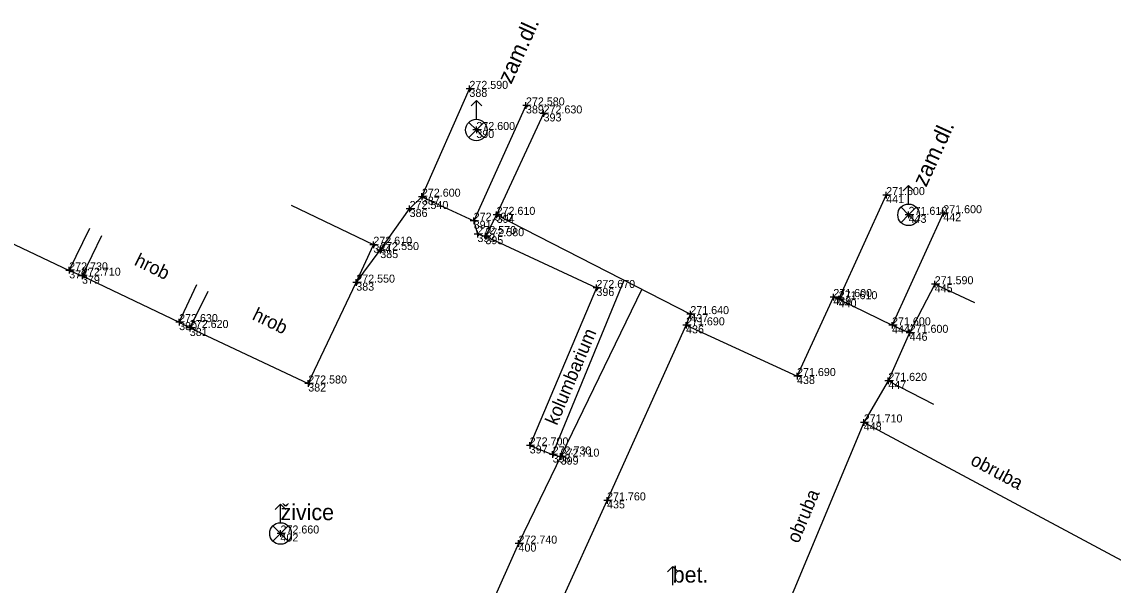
# Model space of a CAD drawing. Extents: x -776606 to -776076, y -974328 to -973875.
# Drawn here: x -776349.29 to -776328.84, y -974207.62 to -974197.06 of the extents above; entities that cross this region are included whole.
import ezdxf

# ---------------------------------------------------------------- set-up
doc = ezdxf.new("R2010")
doc.units = 0
for name, color, linetype in [('Body polohopisu', 7, 'Continuous'), ('Doplňkové značky', 7, 'Continuous'), ('Doplňující texty', 7, 'Continuous'), ('Nezařazené objekty', 7, 'Continuous'), ('Ploty_opěrné zdi', 7, 'Continuous'), ('Rozhraní ploch', 7, 'Continuous'), ('Výšky bodů', 7, 'Continuous'), ('Čísla bodů', 7, 'Continuous')]:
    doc.layers.add(name, color=color, linetype=linetype)

msp = doc.modelspace()

# ---------------------------------------------------------------- linework, layer by layer
at = {"layer": 'Body polohopisu'}
for p, q in [((-776340.9, -974198.32), (-776340.9, -974198.258)), ((-776340.9, -974198.32), (-776340.963, -974198.32)), ((-776340.9, -974198.32), (-776340.838, -974198.32)), ((-776340.9, -974198.32), (-776340.9, -974198.383)), ((-776339.84, -974198.63), (-776339.902, -974198.63)), ((-776339.84, -974198.63), (-776339.84, -974198.568)), ((-776339.84, -974198.63), (-776339.777, -974198.63)), ((-776339.84, -974198.63), (-776339.84, -974198.693)), ((-776339.51, -974198.78), (-776339.573, -974198.78)), ((-776339.51, -974198.78), (-776339.51, -974198.718)), ((-776339.51, -974198.78), (-776339.448, -974198.78)), ((-776339.51, -974198.78), (-776339.51, -974198.843)), ((-776340.77, -974199.09), (-776340.833, -974199.09)), ((-776340.77, -974199.09), (-776340.77, -974199.027)), ((-776340.77, -974199.09), (-776340.708, -974199.09)), ((-776340.77, -974199.09), (-776340.77, -974199.152)), ((-776341.79, -974200.34), (-776341.79, -974200.277)), ((-776333.09, -974200.31), (-776333.152, -974200.31)), ((-776333.09, -974200.31), (-776333.09, -974200.248)), ((-776333.09, -974200.31), (-776333.027, -974200.31)), ((-776333.09, -974200.31), (-776333.09, -974200.373)), ((-776342.02, -974200.57), (-776342.02, -974200.508)), ((-776341.79, -974200.34), (-776341.853, -974200.34)), ((-776341.79, -974200.34), (-776341.728, -974200.34)), ((-776341.79, -974200.34), (-776341.79, -974200.402)), ((-776342.02, -974200.57), (-776342.083, -974200.57)), ((-776342.02, -974200.57), (-776341.958, -974200.57)), ((-776342.02, -974200.57), (-776342.02, -974200.633)), ((-776340.82, -974200.79), (-776340.82, -974200.728)), ((-776340.39, -974200.68), (-776340.453, -974200.68)), ((-776340.39, -974200.68), (-776340.39, -974200.618)), ((-776340.39, -974200.68), (-776340.328, -974200.68)), ((-776340.39, -974200.68), (-776340.39, -974200.743)), ((-776332.67, -974200.68), (-776332.733, -974200.68)), ((-776332.67, -974200.68), (-776332.67, -974200.618)), ((-776332.67, -974200.68), (-776332.608, -974200.68)), ((-776332.67, -974200.68), (-776332.67, -974200.743)), ((-776332.02, -974200.65), (-776332.083, -974200.65)), ((-776332.02, -974200.65), (-776332.02, -974200.588)), ((-776332.02, -974200.65), (-776331.958, -974200.65)), ((-776332.02, -974200.65), (-776332.02, -974200.713)), ((-776340.82, -974200.79), (-776340.883, -974200.79)), ((-776340.82, -974200.79), (-776340.758, -974200.79)), ((-776340.82, -974200.79), (-776340.82, -974200.853)), ((-776340.75, -974201.04), (-776340.812, -974201.04)), ((-776340.75, -974201.04), (-776340.75, -974200.978)), ((-776340.75, -974201.04), (-776340.688, -974201.04)), ((-776340.75, -974201.04), (-776340.75, -974201.103)), ((-776340.6, -974201.08), (-776340.662, -974201.08)), ((-776340.6, -974201.08), (-776340.6, -974201.018)), ((-776340.6, -974201.08), (-776340.537, -974201.08)), ((-776340.6, -974201.08), (-776340.6, -974201.143)), ((-776342.7, -974201.24), (-776342.763, -974201.24)), ((-776342.7, -974201.24), (-776342.7, -974201.177)), ((-776342.7, -974201.24), (-776342.638, -974201.24)), ((-776342.7, -974201.24), (-776342.7, -974201.302)), ((-776342.57, -974201.34), (-776342.633, -974201.34)), ((-776342.57, -974201.34), (-776342.57, -974201.277)), ((-776342.57, -974201.34), (-776342.508, -974201.34)), ((-776342.57, -974201.34), (-776342.57, -974201.402)), ((-776348.4, -974201.72), (-776348.463, -974201.72)), ((-776348.4, -974201.72), (-776348.4, -974201.657)), ((-776348.4, -974201.72), (-776348.338, -974201.72)), ((-776348.4, -974201.72), (-776348.4, -974201.782)), ((-776348.16, -974201.82), (-776348.16, -974201.758)), ((-776348.16, -974201.82), (-776348.223, -974201.82)), ((-776348.16, -974201.82), (-776348.098, -974201.82)), ((-776348.16, -974201.82), (-776348.16, -974201.883)), ((-776343.02, -974201.95), (-776343.083, -974201.95)), ((-776343.02, -974201.95), (-776343.02, -974201.888)), ((-776343.02, -974201.95), (-776342.958, -974201.95)), ((-776343.02, -974201.95), (-776343.02, -974202.013)), ((-776332.18, -974201.98), (-776332.18, -974201.917)), ((-776338.52, -974202.05), (-776338.583, -974202.05)), ((-776338.52, -974202.05), (-776338.52, -974201.988)), ((-776338.52, -974202.05), (-776338.458, -974202.05)), ((-776338.52, -974202.05), (-776338.52, -974202.113)), ((-776334.08, -974202.22), (-776334.08, -974202.157)), ((-776332.18, -974201.98), (-776332.243, -974201.98)), ((-776332.18, -974201.98), (-776332.118, -974201.98)), ((-776332.18, -974201.98), (-776332.18, -974202.042)), ((-776334.08, -974202.22), (-776334.142, -974202.22)), ((-776334.08, -974202.22), (-776334.017, -974202.22)), ((-776334.08, -974202.22), (-776334.08, -974202.282)), ((-776333.98, -974202.26), (-776334.042, -974202.26)), ((-776333.98, -974202.26), (-776333.98, -974202.198)), ((-776333.98, -974202.26), (-776333.917, -974202.26)), ((-776333.98, -974202.26), (-776333.98, -974202.323)), ((-776336.76, -974202.54), (-776336.823, -974202.54)), ((-776336.76, -974202.54), (-776336.76, -974202.478)), ((-776336.76, -974202.54), (-776336.698, -974202.54)), ((-776336.76, -974202.54), (-776336.76, -974202.603)), ((-776346.34, -974202.69), (-776346.402, -974202.69)), ((-776346.34, -974202.69), (-776346.34, -974202.628)), ((-776346.34, -974202.69), (-776346.277, -974202.69)), ((-776346.34, -974202.69), (-776346.34, -974202.753)), ((-776346.14, -974202.8), (-776346.14, -974202.738)), ((-776336.84, -974202.75), (-776336.902, -974202.75)), ((-776336.84, -974202.75), (-776336.84, -974202.688)), ((-776336.84, -974202.75), (-776336.777, -974202.75)), ((-776336.84, -974202.75), (-776336.84, -974202.812)), ((-776332.98, -974202.75), (-776333.042, -974202.75)), ((-776332.98, -974202.75), (-776332.98, -974202.688)), ((-776332.98, -974202.75), (-776332.917, -974202.75)), ((-776332.98, -974202.75), (-776332.98, -974202.812)), ((-776346.14, -974202.8), (-776346.203, -974202.8)), ((-776346.14, -974202.8), (-776346.078, -974202.8)), ((-776346.14, -974202.8), (-776346.14, -974202.863)), ((-776332.65, -974202.89), (-776332.713, -974202.89)), ((-776332.65, -974202.89), (-776332.65, -974202.828)), ((-776332.65, -974202.89), (-776332.588, -974202.89)), ((-776332.65, -974202.89), (-776332.65, -974202.953)), ((-776343.92, -974203.84), (-776343.92, -974203.777)), ((-776334.76, -974203.7), (-776334.823, -974203.7)), ((-776334.76, -974203.7), (-776334.76, -974203.638)), ((-776334.76, -974203.7), (-776334.698, -974203.7)), ((-776334.76, -974203.7), (-776334.76, -974203.763)), ((-776333.05, -974203.79), (-776333.113, -974203.79)), ((-776333.05, -974203.79), (-776333.05, -974203.728)), ((-776333.05, -974203.79), (-776332.988, -974203.79)), ((-776333.05, -974203.79), (-776333.05, -974203.853)), ((-776343.92, -974203.84), (-776343.983, -974203.84)), ((-776343.92, -974203.84), (-776343.858, -974203.84)), ((-776343.92, -974203.84), (-776343.92, -974203.902)), ((-776333.51, -974204.57), (-776333.573, -974204.57)), ((-776333.51, -974204.57), (-776333.51, -974204.508)), ((-776333.51, -974204.57), (-776333.448, -974204.57)), ((-776333.51, -974204.57), (-776333.51, -974204.633)), ((-776339.77, -974205), (-776339.833, -974205)), ((-776339.77, -974205), (-776339.77, -974204.938)), ((-776339.77, -974205), (-776339.708, -974205)), ((-776339.77, -974205), (-776339.77, -974205.062)), ((-776339.34, -974205.17), (-776339.402, -974205.17)), ((-776339.34, -974205.17), (-776339.34, -974205.108)), ((-776339.34, -974205.17), (-776339.277, -974205.17)), ((-776339.34, -974205.17), (-776339.34, -974205.233)), ((-776339.19, -974205.21), (-776339.253, -974205.21)), ((-776339.19, -974205.21), (-776339.19, -974205.147)), ((-776339.19, -974205.21), (-776339.128, -974205.21)), ((-776339.19, -974205.21), (-776339.19, -974205.272)), ((-776338.32, -974206.03), (-776338.383, -974206.03)), ((-776338.32, -974206.03), (-776338.32, -974205.968)), ((-776338.32, -974206.03), (-776338.258, -974206.03)), ((-776338.32, -974206.03), (-776338.32, -974206.093)), ((-776344.44, -974206.65), (-776344.503, -974206.65)), ((-776344.44, -974206.65), (-776344.44, -974206.588)), ((-776344.44, -974206.65), (-776344.378, -974206.65)), ((-776344.44, -974206.65), (-776344.44, -974206.713)), ((-776339.98, -974206.84), (-776340.042, -974206.84)), ((-776339.98, -974206.84), (-776339.98, -974206.777)), ((-776339.98, -974206.84), (-776339.917, -974206.84)), ((-776339.98, -974206.84), (-776339.98, -974206.902))]:
    msp.add_line(p, q, dxfattribs=at)
at = {"layer": 'Doplňkové značky'}
for p, q in [((-776340.77, -974198.54), (-776340.87, -974198.64)), ((-776340.77, -974198.888), (-776340.77, -974198.54)), ((-776340.77, -974198.54), (-776340.67, -974198.64)), ((-776340.77, -974199.09), (-776340.912, -974198.948)), ((-776340.77, -974199.09), (-776340.912, -974199.232)), ((-776340.77, -974199.09), (-776340.628, -974198.948)), ((-776340.77, -974199.09), (-776340.77, -974199.09)), ((-776340.77, -974199.09), (-776340.628, -974199.232)), ((-776332.67, -974200.13), (-776332.77, -974200.23)), ((-776332.67, -974200.478), (-776332.67, -974200.13)), ((-776332.67, -974200.13), (-776332.57, -974200.23)), ((-776332.67, -974200.68), (-776332.812, -974200.537)), ((-776332.67, -974200.68), (-776332.527, -974200.537)), ((-776332.67, -974200.68), (-776332.812, -974200.822)), ((-776332.67, -974200.68), (-776332.67, -974200.68)), ((-776332.67, -974200.68), (-776332.527, -974200.822)), ((-776344.44, -974206.1), (-776344.54, -974206.2)), ((-776344.44, -974206.448), (-776344.44, -974206.1)), ((-776344.44, -974206.1), (-776344.34, -974206.2)), ((-776344.44, -974206.65), (-776344.582, -974206.508)), ((-776344.44, -974206.65), (-776344.582, -974206.792)), ((-776344.44, -974206.65), (-776344.297, -974206.508)), ((-776344.44, -974206.65), (-776344.44, -974206.65)), ((-776344.44, -974206.65), (-776344.297, -974206.792)), ((-776337.09, -974207.27), (-776337.189, -974207.37)), ((-776337.09, -974207.618), (-776337.09, -974207.27)), ((-776337.09, -974207.27), (-776336.99, -974207.37))]:
    msp.add_line(p, q, dxfattribs=at)
for centre in [(-776340.77, -974199.09), (-776332.67, -974200.68), (-776344.44, -974206.65)]:
    msp.add_circle(centre, 0.202, dxfattribs=at)
at = {"layer": 'Nezařazené objekty'}
for points in [[(-776336.84, -974202.75), (-776334.76, -974203.7), (-776334.08, -974202.22)], [(-776333.51, -974204.57), (-776335.36, -974209), (-776335.49, -974209.19), (-776333.21, -974211.03), (-776333.04, -974210.85), (-776328.22, -974207.51), (-776328.32, -974207.35), (-776333.51, -974204.57)]]:
    msp.add_lwpolyline(points, dxfattribs=at)
at = {"layer": 'Ploty_opěrné zdi'}
for p, q in [((-776340.39, -974200.68), (-776336.76, -974202.54)), ((-776340.38, -974210.57), (-776338.32, -974206.03))]:
    msp.add_line(p, q, dxfattribs=at)
for points in [[(-776340.39, -974200.68), (-776340.6, -974201.08), (-776338.52, -974202.05), (-776339.77, -974205), (-776339.34, -974205.17), (-776337.997, -974201.906)], [(-776337.67, -974202.074), (-776339.98, -974206.84), (-776341.62, -974210.53), (-776341.1, -974210.76), (-776340.93, -974210.48)], [(-776338.32, -974206.03), (-776336.84, -974202.75), (-776336.76, -974202.54)]]:
    msp.add_lwpolyline(points, dxfattribs=at)
at = {"layer": 'Rozhraní ploch'}
for points in [[(-776356.05, -974198.15), (-776354.87, -974198.67), (-776353.8, -974199.15), (-776353.71, -974199), (-776353.02, -974199.36), (-776353.11, -974199.49), (-776348.4, -974201.72), (-776348.011, -974200.932)], [(-776341.79, -974200.34), (-776340.9, -974198.32)], [(-776339.84, -974198.63), (-776340.82, -974200.79)], [(-776339.51, -974198.78), (-776340.39, -974200.68)], [(-776333.98, -974202.26), (-776333.09, -974200.31)], [(-776345.804, -974202.117), (-776346.14, -974202.8), (-776343.92, -974203.84), (-776343.02, -974201.95), (-776342.7, -974201.24), (-776344.236, -974200.508)], [(-776343.02, -974201.95), (-776342.57, -974201.34), (-776342.02, -974200.57), (-776341.79, -974200.34), (-776340.82, -974200.79), (-776340.75, -974201.04), (-776340.6, -974201.08)], [(-776332.02, -974200.65), (-776332.98, -974202.75)], [(-776347.796, -974201.074), (-776348.16, -974201.82), (-776346.34, -974202.69), (-776346.009, -974201.985)], [(-776348.4, -974201.72), (-776348.16, -974201.82)], [(-776331.427, -974202.327), (-776332.18, -974201.98), (-776332.65, -974202.89), (-776333.05, -974203.79), (-776332.203, -974204.224)], [(-776334.08, -974202.22), (-776333.98, -974202.26), (-776332.98, -974202.75), (-776332.65, -974202.89)], [(-776346.34, -974202.69), (-776346.14, -974202.8)], [(-776333.05, -974203.79), (-776333.51, -974204.57)], [(-776339.34, -974205.17), (-776339.19, -974205.21)]]:
    msp.add_lwpolyline(points, dxfattribs=at)

# ---------------------------------------------------------------- texts
at = {"layer": 'Doplňující texty'}
for s, height, rotation, p in [('zam.dl.', 0.3, 65.596, (-776340.117, -974198.246)), ('zam.dl.', 0.3, 65.4328, (-776332.341, -974200.175)), ('hrob', 0.25, 333.9465, (-776347.197, -974201.612)), ('hrob', 0.25, 333.9465, (-776344.987, -974202.631)), ('kolumbarium', 0.25, 67.0362, (-776339.26, -974204.638)), ('obruba', 0.25, 331.8245, (-776331.53, -974205.347)), ('obruba', 0.25, 67.3342, (-776334.733, -974206.849))]:
    msp.add_text(s, height=height, rotation=rotation, dxfattribs=at).set_placement(p)
for s, p in [('živice', (-776344.44, -974206.4)), ('bet.', (-776337.09, -974207.57))]:
    msp.add_text(s, height=0.3, dxfattribs=at).set_placement(p)
at = {"layer": 'Výšky bodů'}
for s, p in [('272.590', (-776340.9, -974198.32)), ('272.580', (-776339.84, -974198.63)), ('272.630', (-776339.51, -974198.78)), ('272.600', (-776340.77, -974199.09)), ('272.600', (-776341.79, -974200.34)), ('271.600', (-776333.09, -974200.31)), ('272.540', (-776342.02, -974200.57)), ('272.610', (-776340.39, -974200.68)), ('271.610', (-776332.67, -974200.68)), ('271.600', (-776332.02, -974200.65)), ('272.590', (-776340.82, -974200.79)), ('272.570', (-776340.75, -974201.04)), ('272.580', (-776340.6, -974201.08)), ('272.610', (-776342.7, -974201.24)), ('272.550', (-776342.57, -974201.34)), ('272.730', (-776348.4, -974201.72)), ('272.710', (-776348.16, -974201.82)), ('272.550', (-776343.02, -974201.95)), ('272.670', (-776338.52, -974202.05)), ('271.590', (-776332.18, -974201.98)), ('271.600', (-776334.08, -974202.22)), ('271.610', (-776333.98, -974202.26)), ('272.630', (-776346.34, -974202.69)), ('271.640', (-776336.76, -974202.54)), ('272.620', (-776346.14, -974202.8)), ('271.690', (-776336.84, -974202.75)), ('271.600', (-776332.98, -974202.75)), ('271.600', (-776332.65, -974202.89)), ('271.690', (-776334.76, -974203.7)), ('272.580', (-776343.92, -974203.84)), ('271.620', (-776333.05, -974203.79)), ('271.710', (-776333.51, -974204.57)), ('272.700', (-776339.77, -974205)), ('272.730', (-776339.34, -974205.17)), ('272.710', (-776339.19, -974205.21)), ('271.760', (-776338.32, -974206.03)), ('272.660', (-776344.44, -974206.65)), ('272.740', (-776339.98, -974206.84))]:
    msp.add_text(s, height=0.15, dxfattribs=at).set_placement(p)
at = {"layer": 'Čísla bodů'}
for s, p in [('388', (-776340.9, -974198.47)), ('389', (-776339.84, -974198.78)), ('393', (-776339.51, -974198.93)), ('390', (-776340.77, -974199.24)), ('387', (-776341.79, -974200.49)), ('441', (-776333.09, -974200.46)), ('386', (-776342.02, -974200.72)), ('394', (-776340.39, -974200.83)), ('443', (-776332.67, -974200.83)), ('442', (-776332.02, -974200.8)), ('391', (-776340.82, -974200.94)), ('392', (-776340.75, -974201.19)), ('395', (-776340.6, -974201.23)), ('384', (-776342.7, -974201.39)), ('385', (-776342.57, -974201.49)), ('378', (-776348.4, -974201.87)), ('379', (-776348.16, -974201.97)), ('383', (-776343.02, -974202.1)), ('396', (-776338.52, -974202.2)), ('445', (-776332.18, -974202.13)), ('439', (-776334.08, -974202.37)), ('440', (-776333.98, -974202.41)), ('437', (-776336.76, -974202.69)), ('380', (-776346.34, -974202.84)), ('436', (-776336.84, -974202.9)), ('444', (-776332.98, -974202.9)), ('381', (-776346.14, -974202.95)), ('446', (-776332.65, -974203.04)), ('438', (-776334.76, -974203.85)), ('447', (-776333.05, -974203.94)), ('382', (-776343.92, -974203.99)), ('448', (-776333.51, -974204.72)), ('397', (-776339.77, -974205.15)), ('398', (-776339.34, -974205.32)), ('399', (-776339.19, -974205.36)), ('435', (-776338.32, -974206.18)), ('402', (-776344.44, -974206.8)), ('400', (-776339.98, -974206.99))]:
    msp.add_text(s, height=0.15, dxfattribs=at).set_placement(p)

doc.saveas('drawing.dxf')
